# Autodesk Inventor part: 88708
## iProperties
Created: 2005-12
Part Number: 88708
Material: 1.4301 X5CrNi10-10 A2
Document SubType Name: Modellieren
Designer: Mittelmeyer
Manufacturer: Standard
Standards Organization: Custom
Description: Zentrierring (A2/FPM) DN 250 ISO-K
Vendor: LEYBOLD
Author: Mittelmeyer
Comments: LEYBOLD
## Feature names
1. Extrusion2
2. Bohrung1 [Hole]
3. Extrusion3
4. Spiegeln1 [Mirror]
